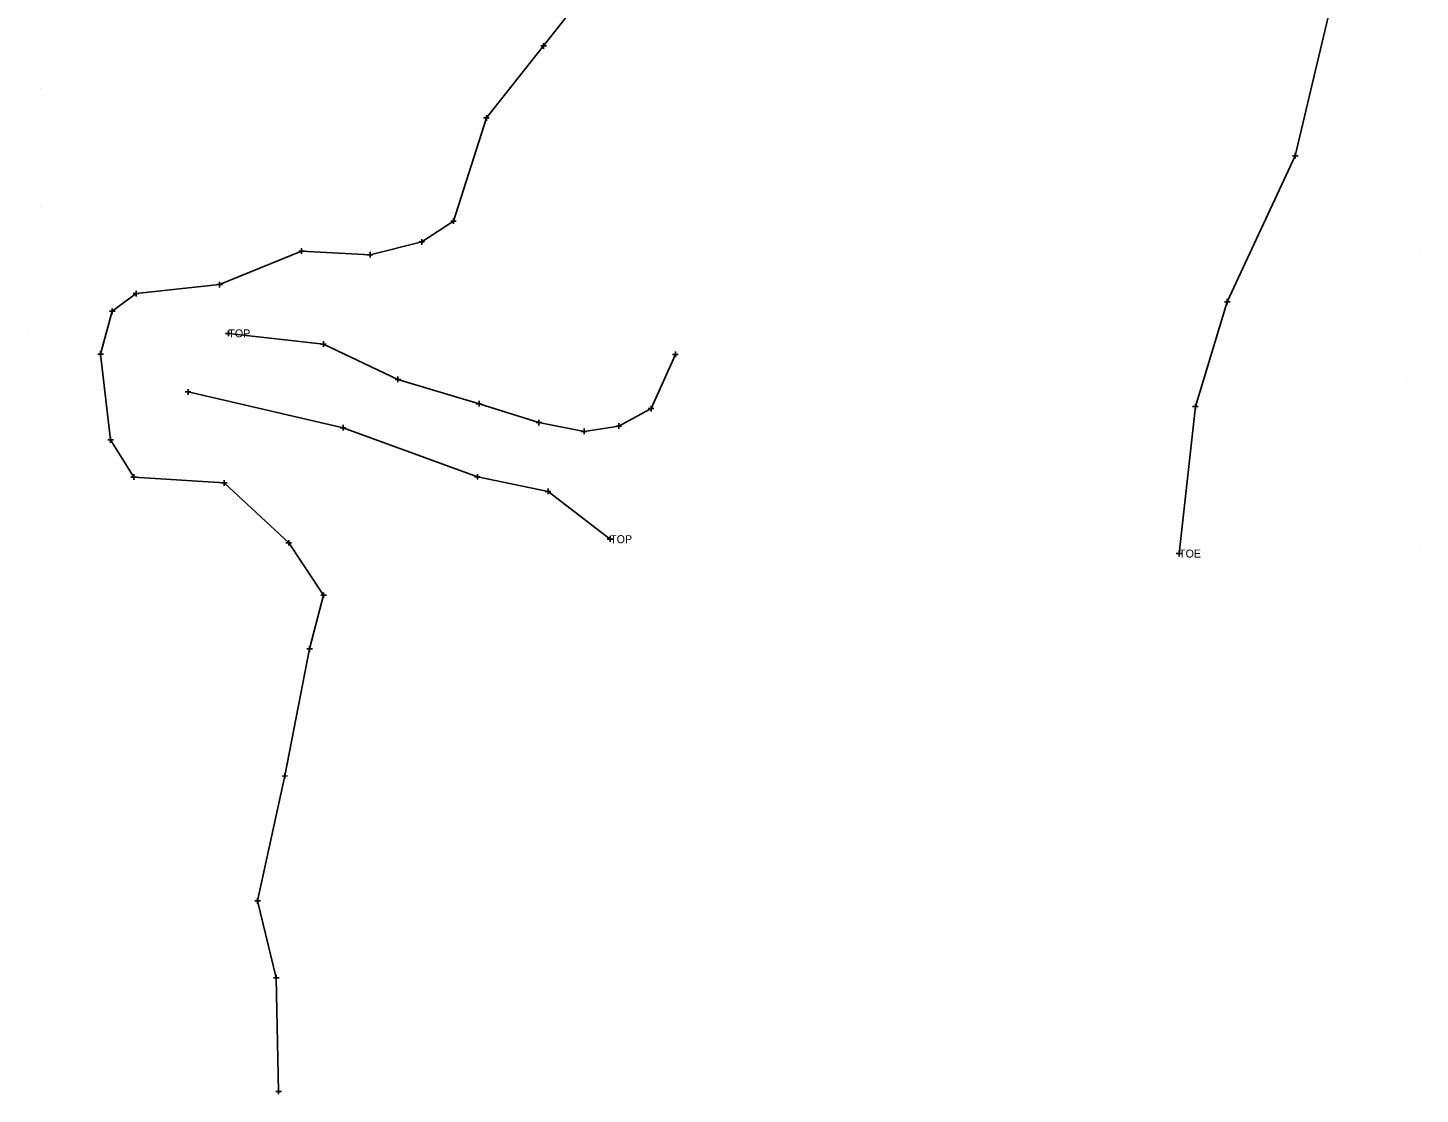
# Model space of a CAD drawing. Extents: x 1738496 to 1739092, y 463766 to 465141.
# Drawn here: x 1738547.2 to 1738860.4, y 464103.9 to 464343.8 of the extents above; entities that cross this region are included whole.
import ezdxf

# ---------------------------------------------------------------- set-up
doc = ezdxf.new("R2010")
doc.units = 0
for name, color, linetype in [('S_Survey_Shot', 7, 'Continuous'), ('S_Terrain_Low_Points', 7, 'Continuous'), ('S_Terrain_Triangles', 7, 'Continuous'), ('S_Terrain_XSC', 7, 'Continuous')]:
    doc.layers.add(name, color=color, linetype=linetype)

msp = doc.modelspace()

# ---------------------------------------------------------------- linework, layer by layer
at = {"layer": 'S_Terrain_Low_Points'}
for points in [[(1738806.18, 464225.49), (1738809.88, 464258.56), (1738817.03, 464282.16), (1738832.34, 464314.98), (1738840.08, 464347.84), (1738855.97, 464392.7), (1738854.17, 464418.77), (1738856.11, 464447.99)], [(1738672.82, 464351.98), (1738663.2, 464339.71), (1738650.35, 464323.52), (1738642.94, 464300.29), (1738635.79, 464295.6), (1738624.17, 464292.72), (1738608.77, 464293.55), (1738590.31, 464286.01), (1738571.55, 464284), (1738566.17, 464280), (1738563.53, 464270.39), (1738565.8, 464251.07), (1738570.99, 464242.68), (1738591.36, 464241.39), (1738605.89, 464227.91), (1738613.7, 464216.14), (1738610.57, 464204.05), (1738604.99, 464175.45), (1738598.87, 464147.33), (1738603.06, 464130.07), (1738603.58, 464104.5)], [(1738592.29, 464275.04), (1738613.69, 464272.62), (1738630.44, 464264.67), (1738648.69, 464259.2), (1738662.17, 464254.96), (1738672.33, 464252.96), (1738680.11, 464254.18), (1738687.38, 464258.1), (1738692.88, 464270.31)], [(1738678.18, 464228.73), (1738664.22, 464239.47), (1738648.33, 464242.76), (1738618.09, 464253.81), (1738583.22, 464261.86)]]:
    msp.add_lwpolyline(points, dxfattribs=at)
at = {"layer": 'S_Terrain_Triangles'}
for p, q in [((1738550.12, 464330.05), (1738550.12, 464330.05)), ((1738550.04, 464303.58), (1738550.04, 464303.58)), ((1738860.31, 464294.14), (1738860.31, 464294.14)), ((1738547.18, 464275), (1738547.18, 464275)), ((1738857.4, 464264.22), (1738857.4, 464264.22)), ((1738860.42, 464226.44), (1738860.42, 464226.44))]:
    msp.add_line(p, q, dxfattribs=at)
at = {"layer": 'S_Terrain_XSC'}
for p, q in [((1738662.56, 464339.71), (1738663.84, 464339.71)), ((1738663.2, 464339.08), (1738663.2, 464340.35)), ((1738663.2, 464339.71), (1738663.2, 464339.71)), ((1738649.71, 464323.51), (1738650.98, 464323.52)), ((1738650.35, 464322.88), (1738650.35, 464324.15)), ((1738650.35, 464323.52), (1738650.35, 464323.52)), ((1738831.7, 464314.98), (1738832.98, 464314.98)), ((1738832.34, 464314.35), (1738832.34, 464315.62)), ((1738832.34, 464314.98), (1738832.34, 464314.98)), ((1738642.31, 464300.28), (1738643.58, 464300.29)), ((1738642.95, 464299.65), (1738642.94, 464300.92)), ((1738642.94, 464300.29), (1738642.94, 464300.29)), ((1738635.15, 464295.6), (1738636.42, 464295.6)), ((1738635.79, 464294.96), (1738635.79, 464296.24)), ((1738635.79, 464295.6), (1738635.79, 464295.6)), ((1738608.14, 464293.55), (1738609.41, 464293.55)), ((1738608.77, 464292.92), (1738608.77, 464294.19)), ((1738608.77, 464293.55), (1738608.77, 464293.55)), ((1738623.53, 464292.72), (1738624.81, 464292.72)), ((1738624.17, 464292.08), (1738624.17, 464293.35)), ((1738624.17, 464292.72), (1738624.17, 464292.72)), ((1738589.67, 464286), (1738590.95, 464286.01)), ((1738590.31, 464285.37), (1738590.31, 464286.64)), ((1738590.31, 464286.01), (1738590.31, 464286.01)), ((1738570.91, 464284), (1738572.19, 464284)), ((1738571.55, 464283.36), (1738571.55, 464284.63)), ((1738571.55, 464284), (1738571.55, 464284)), ((1738817.03, 464281.52), (1738817.02, 464282.79)), ((1738565.53, 464280), (1738566.8, 464280)), ((1738566.17, 464279.36), (1738566.17, 464280.64)), ((1738566.17, 464280), (1738566.17, 464280)), ((1738816.39, 464282.16), (1738817.66, 464282.16)), ((1738817.03, 464282.16), (1738817.03, 464282.16)), ((1738591.65, 464275.04), (1738592.92, 464275.04)), ((1738592.29, 464274.4), (1738592.29, 464275.67)), ((1738592.29, 464275.04), (1738592.29, 464275.04)), ((1738562.9, 464270.39), (1738564.17, 464270.39)), ((1738563.53, 464269.75), (1738563.53, 464271.02)), ((1738563.53, 464270.39), (1738563.53, 464270.39)), ((1738613.05, 464272.61), (1738614.32, 464272.62)), ((1738613.69, 464271.98), (1738613.69, 464273.25)), ((1738613.69, 464272.62), (1738613.69, 464272.62)), ((1738692.25, 464270.31), (1738693.52, 464270.31)), ((1738692.88, 464269.67), (1738692.88, 464270.95)), ((1738692.88, 464270.31), (1738692.88, 464270.31)), ((1738629.8, 464264.67), (1738631.07, 464264.67)), ((1738630.44, 464264.03), (1738630.44, 464265.3)), ((1738630.44, 464264.67), (1738630.44, 464264.67)), ((1738582.59, 464261.86), (1738583.86, 464261.86)), ((1738583.23, 464261.22), (1738583.22, 464262.5)), ((1738583.22, 464261.86), (1738583.22, 464261.86)), ((1738648.06, 464259.2), (1738649.33, 464259.2)), ((1738648.69, 464258.56), (1738648.69, 464259.84)), ((1738648.69, 464259.2), (1738648.69, 464259.2)), ((1738686.75, 464258.1), (1738688.02, 464258.1)), ((1738687.39, 464257.46), (1738687.38, 464258.74)), ((1738687.38, 464258.1), (1738687.38, 464258.1)), ((1738809.24, 464258.56), (1738810.51, 464258.56)), ((1738809.88, 464257.92), (1738809.87, 464259.2)), ((1738809.88, 464258.56), (1738809.88, 464258.56)), ((1738661.53, 464254.96), (1738662.8, 464254.96)), ((1738662.17, 464254.33), (1738662.17, 464255.6)), ((1738662.17, 464254.96), (1738662.17, 464254.96)), ((1738680.12, 464253.54), (1738680.11, 464254.82)), ((1738565.8, 464250.44), (1738565.79, 464251.71)), ((1738617.46, 464253.81), (1738618.73, 464253.81)), ((1738618.09, 464253.18), (1738618.09, 464254.45)), ((1738618.09, 464253.81), (1738618.09, 464253.81)), ((1738671.69, 464252.96), (1738672.96, 464252.96)), ((1738672.33, 464252.32), (1738672.33, 464253.6)), ((1738672.33, 464252.96), (1738672.33, 464252.96)), ((1738679.48, 464254.18), (1738680.75, 464254.18)), ((1738680.11, 464254.18), (1738680.11, 464254.18)), ((1738565.16, 464251.07), (1738566.43, 464251.07)), ((1738565.8, 464251.07), (1738565.8, 464251.07)), ((1738570.35, 464242.68), (1738571.62, 464242.69)), ((1738570.99, 464242.05), (1738570.99, 464243.32)), ((1738570.99, 464242.68), (1738570.99, 464242.68)), ((1738591.36, 464240.76), (1738591.36, 464242.03)), ((1738647.69, 464242.76), (1738648.97, 464242.76)), ((1738648.33, 464242.12), (1738648.33, 464243.39)), ((1738648.33, 464242.76), (1738648.33, 464242.76)), ((1738590.72, 464241.39), (1738592, 464241.39)), ((1738591.36, 464241.39), (1738591.36, 464241.39)), ((1738663.59, 464239.47), (1738664.86, 464239.47)), ((1738664.23, 464238.84), (1738664.22, 464240.11)), ((1738664.22, 464239.47), (1738664.22, 464239.47)), ((1738605.25, 464227.91), (1738606.53, 464227.91)), ((1738605.89, 464227.27), (1738605.89, 464228.54)), ((1738605.89, 464227.91), (1738605.89, 464227.91)), ((1738677.55, 464228.73), (1738678.82, 464228.73)), ((1738678.18, 464228.1), (1738678.18, 464229.37)), ((1738678.18, 464228.73), (1738678.18, 464228.73)), ((1738805.54, 464225.49), (1738806.81, 464225.49)), ((1738806.18, 464224.85), (1738806.17, 464226.13)), ((1738806.18, 464225.49), (1738806.18, 464225.49)), ((1738613.07, 464216.14), (1738614.34, 464216.14)), ((1738613.71, 464215.5), (1738613.7, 464216.77)), ((1738613.7, 464216.14), (1738613.7, 464216.14)), ((1738610.57, 464203.41), (1738610.57, 464204.68)), ((1738609.94, 464204.05), (1738611.21, 464204.05)), ((1738610.57, 464204.05), (1738610.57, 464204.05)), ((1738604.36, 464175.44), (1738605.63, 464175.45)), ((1738604.99, 464174.81), (1738604.99, 464176.08)), ((1738604.99, 464175.45), (1738604.99, 464175.45)), ((1738598.87, 464146.7), (1738598.86, 464147.97)), ((1738598.23, 464147.33), (1738599.5, 464147.34)), ((1738598.87, 464147.33), (1738598.87, 464147.33)), ((1738602.42, 464130.07), (1738603.69, 464130.07)), ((1738603.06, 464129.43), (1738603.06, 464130.7)), ((1738603.06, 464130.07), (1738603.06, 464130.07)), ((1738602.94, 464104.5), (1738604.22, 464104.5)), ((1738603.58, 464103.87), (1738603.58, 464105.14)), ((1738603.58, 464104.5), (1738603.58, 464104.5))]:
    msp.add_line(p, q, dxfattribs=at)

# ---------------------------------------------------------------- texts
at = {"layer": 'S_Survey_Shot'}
for s, p in [('TOP', (1738592.29, 464274.14)), ('TOP', (1738678.18, 464227.83)), ('TOE', (1738806.18, 464224.59))]:
    msp.add_text(s, height=1.8, dxfattribs=at).set_placement(p)

doc.saveas('drawing.dxf')
